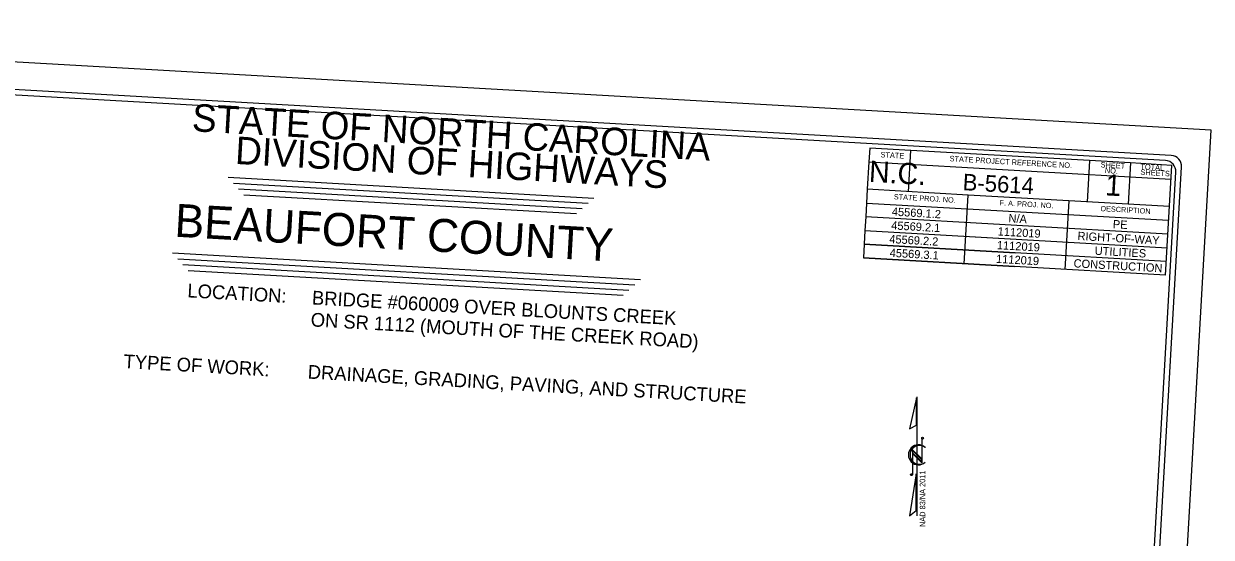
# Model space of a CAD drawing. Extents: x 2601627 to 2606907, y 616646 to 620530.
# Drawn here: x 2603669 to 2606907, y 619130 to 620530 of the extents above; entities that cross this region are included whole.
import ezdxf

# ---------------------------------------------------------------- set-up
doc = ezdxf.new("R2010")
doc.units = 0
for name, color, linetype in [('Sheet Data Field CELL', 7, 'Continuous'), ('Sheet North Arrow CELL', 7, 'Continuous'), ('Sheet Title CELL', 7, 'Continuous'), ('Stewart Plot Border Xerox6279 and LJ5000', 7, 'Continuous')]:
    doc.layers.add(name, color=color, linetype=linetype)

msp = doc.modelspace()

# ---------------------------------------------------------------- linework, layer by layer
at = {"layer": 'Sheet North Arrow CELL'}
for p, q in [((2606104.8, 619187.6), (2606104.8, 619512.6)), ((2606117.1, 619399.5), (2606117.1, 619332.8)), ((2606117.1, 619343.2), (2606092.2, 619368.1)), ((2606092.2, 619368.1), (2606092.2, 619300.3)), ((2606117.1, 619340.8), (2606092.2, 619365.6)), ((2606092.2, 619365.6), (2606092.2, 619359.5)), ((2606117.1, 619334.7), (2606092.2, 619359.5)), ((2606092.2, 619359.5), (2606117.1, 619334.7)), ((2606117.1, 619332.8), (2606092.2, 619357.7)), ((2606126.3, 619374.7), (2606126.6, 619374.4)), ((2606117.1, 619334.7), (2606117.1, 619340.8))]:
    msp.add_line(p, q, dxfattribs=at)
for points in [[(2606102.6, 619509.8), (2606084, 619425.4), (2606102.6, 619434.8)], [(2606102.2, 619302.1), (2606083.7, 619187.6), (2606102.1, 619202.1)]]:
    msp.add_lwpolyline(points, close=True, dxfattribs=at)
for centre in [(2606119.7, 619399.5), (2606089.6, 619300.2)]:
    msp.add_circle(centre, 2.65, dxfattribs=at)
for centre, radius, start, end in [((2606108.3, 619354.2), 27.3, 47.8283, 312.3824), ((2606110.9, 619354.2), 25.6, 53.0833, 308.617)]:
    msp.add_arc(centre, radius, start, end, dxfattribs=at)
at = {"layer": 'Sheet Title CELL'}
for p, q in [((2605975.3, 620190.3), (2605973.1, 620152.9)), ((2606087.6, 620184), (2605975.3, 620190.3)), ((2606081.2, 620071.6), (2606087.6, 620184)), ((2606574.3, 620156.3), (2606087.6, 620184)), ((2605973.1, 620152.9), (2605968.9, 620078.1)), ((2605973.1, 620152.9), (2606796.8, 620106)), ((2606574.3, 620156.2), (2606567.9, 620043.9)), ((2606686.6, 620149.9), (2606574.3, 620156.3)), ((2606686.6, 620149.9), (2606680.3, 620037.5)), ((2606798.9, 620143.5), (2606686.6, 620149.9)), ((2606781.9, 619844), (2606798.9, 620143.5)), ((2604226.6, 620111), (2605223.3, 620054.3)), ((2604240.8, 620095.2), (2605207.5, 620040.1)), ((2604254.9, 620079.3), (2605191.6, 620026)), ((2605968.9, 620078.1), (2605966.7, 620040.6)), ((2606243.4, 620062.4), (2605968.9, 620078.1)), ((2604269, 620063.5), (2605175.8, 620011.9)), ((2605966.7, 620040.6), (2605964.6, 620003.2)), ((2605966.7, 620040.6), (2606790.4, 619993.7)), ((2606232.7, 619875.3), (2606243.4, 620062.4)), ((2606517.9, 620046.8), (2606243.4, 620062.4)), ((2606517.9, 620046.8), (2606507.2, 619859.6)), ((2606792.5, 620031.2), (2606517.9, 620046.8)), ((2605964.6, 620003.2), (2605962.5, 619965.7)), ((2606788.3, 619956.2), (2605964.6, 620003.2)), ((2605962.5, 619965.7), (2605960.3, 619928.3)), ((2605962.5, 619965.8), (2606374.3, 619942.3)), ((2605962.5, 619965.7), (2606786.1, 619918.8)), ((2604074.7, 619904.5), (2605350.6, 619831.8)), ((2605960.3, 619928.3), (2605958.2, 619890.9)), ((2606784, 619881.4), (2605960.3, 619928.3)), ((2605960.3, 619928.3), (2606372.2, 619904.9)), ((2604088.8, 619888.7), (2605334.8, 619817.7)), ((2604103, 619872.8), (2605319, 619803.6)), ((2606781.9, 619844), (2605958.2, 619890.9)), ((2605958.2, 619890.9), (2606370, 619867.5)), ((2604117.1, 619857.1), (2605303.2, 619789.5))]:
    msp.add_line(p, q, dxfattribs=at)
for points in [[(2606797.5, 620170.6), (2602364.6, 620423.1)], [(2606781.6, 620156.4), (2602528.6, 620398.7)], [(2606650, 617053.9), (2606825.7, 620138.9)], [(2606667.4, 617623.8), (2606809.9, 620124.8)]]:
    msp.add_lwpolyline(points, dxfattribs=at)
for centre in [(2606795.8, 620140.8), (2606780, 620126.7)]:
    msp.add_arc(centre, 30, 356.7403, 86.7403, dxfattribs=at)
at = {"layer": 'Stewart Plot Border Xerox6279 and LJ5000'}
msp.add_lwpolyline([(2601627.1, 617234.9), (2606718.9, 616944.8), (2606906.6, 620239.5), (2601814.8, 620529.5)], close=True, dxfattribs=at)

# ---------------------------------------------------------------- texts
at = {"layer": 'Sheet Data Field CELL'}
for s, height, p in [('B-5614', 45, (2606228, 620075.9)), ('BEAUFORT COUNTY', 90, (2604078.7, 619949.1)), ('45569.1.2', 22.5, (2606035.3, 620006.5)), ('N/A', 22.5, (2606353.2, 619988.4)), ('45569.2.1', 22.5, (2606033.6, 619969)), ('1112019', 22.5, (2606323.8, 619952.5)), ('PE', 22.5, (2606637.7, 619972.2)), ('45569.2.2', 22.5, (2606028.3, 619931.8)), ('1112019', 22.5, (2606321.7, 619915.1)), ('RIGHT-OF-WAY', 22.5, (2606541.5, 619940.1)), ('45569.3.1', 22.5, (2606029.4, 619894.2)), ('UTILITIES', 22.5, (2606588.3, 619899.9)), ('1112019', 22.5, (2606319.5, 619877.7)), ('CONSTRUCTION', 22.5, (2606530.8, 619865.6)), ('BRIDGE #060009 OVER BLOUNTS CREEK', 37.5, (2604454, 619764.4)), ('ON SR 1112 (MOUTH OF THE CREEK ROAD)', 37.5, (2604450.6, 619704.5)), ('DRAINAGE, GRADING, PAVING, AND STRUCTURE', 37.5, (2604442.5, 619562.2))]:
    msp.add_text(s, height=height, rotation=356.7403, dxfattribs=at).set_placement(p)
at = {"layer": 'Sheet North Arrow CELL'}
msp.add_text('NAD 83/NA 2011', height=15, rotation=89.9883, dxfattribs=at).set_placement((2606126.8, 619157.5))
at = {"layer": 'Sheet Title CELL'}
for s, height, p in [('STATE OF NORTH CAROLINA', 75, (2604126.2, 620236.8)), ('DIVISION OF HIGHWAYS', 75, (2604244, 620147.5)), ('STATE', 15, (2606004.6, 620165.4)), ('STATE PROJECT REFERENCE NO.', 14.999, (2606192.9, 620154.7)), ('N.C.', 58.05, (2605972.3, 620098.5)), ('SHEET', 15, (2606604.7, 620138)), ('NO.', 15, (2606616.2, 620122.5)), ('TOTAL', 15, (2606713.1, 620132.9)), ('SHEETS', 15, (2606713.3, 620117.9)), ('1', 58.1, (2606616.5, 620061.8)), ('STATE PROJ. NO.', 14.4, (2606040.8, 620051)), ('F. A. PROJ. NO.', 14.4, (2606329.2, 620034.6)), ('DESCRIPTION', 14.4, (2606605.1, 620018.8)), ('LOCATION:', 37.5, (2604114.5, 619783.7)), ('TYPE OF WORK:', 37.5, (2603940.4, 619590.8))]:
    msp.add_text(s, height=height, rotation=356.7403, dxfattribs=at).set_placement(p)

doc.saveas('drawing.dxf')
